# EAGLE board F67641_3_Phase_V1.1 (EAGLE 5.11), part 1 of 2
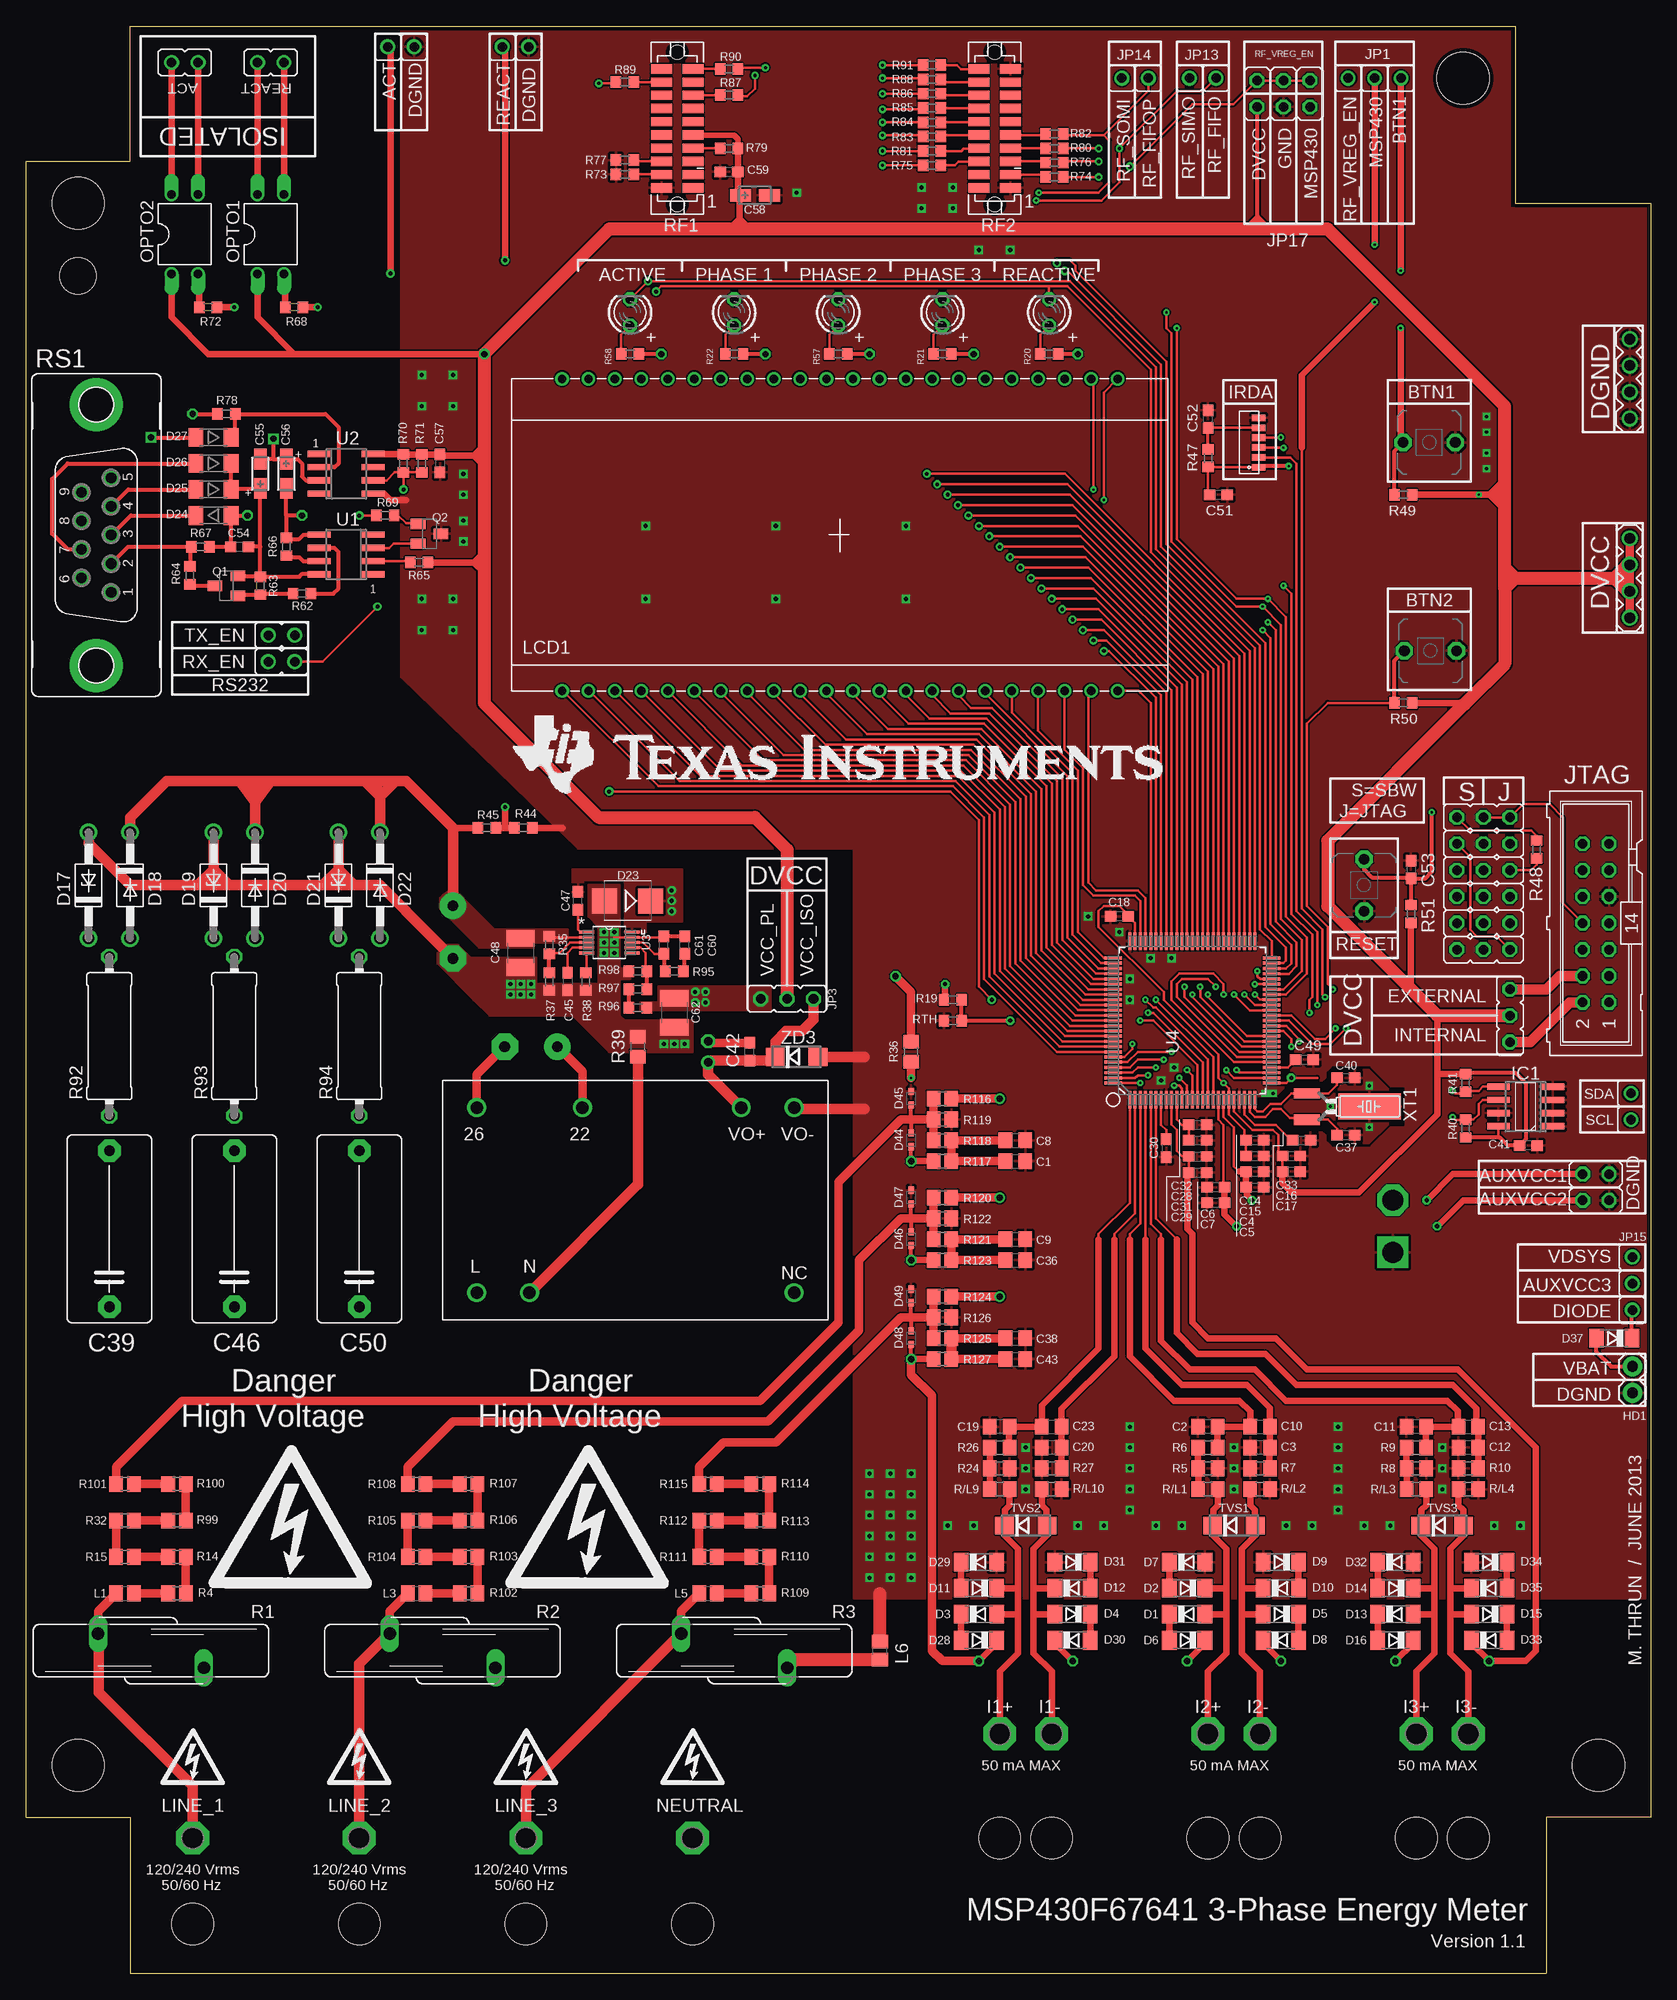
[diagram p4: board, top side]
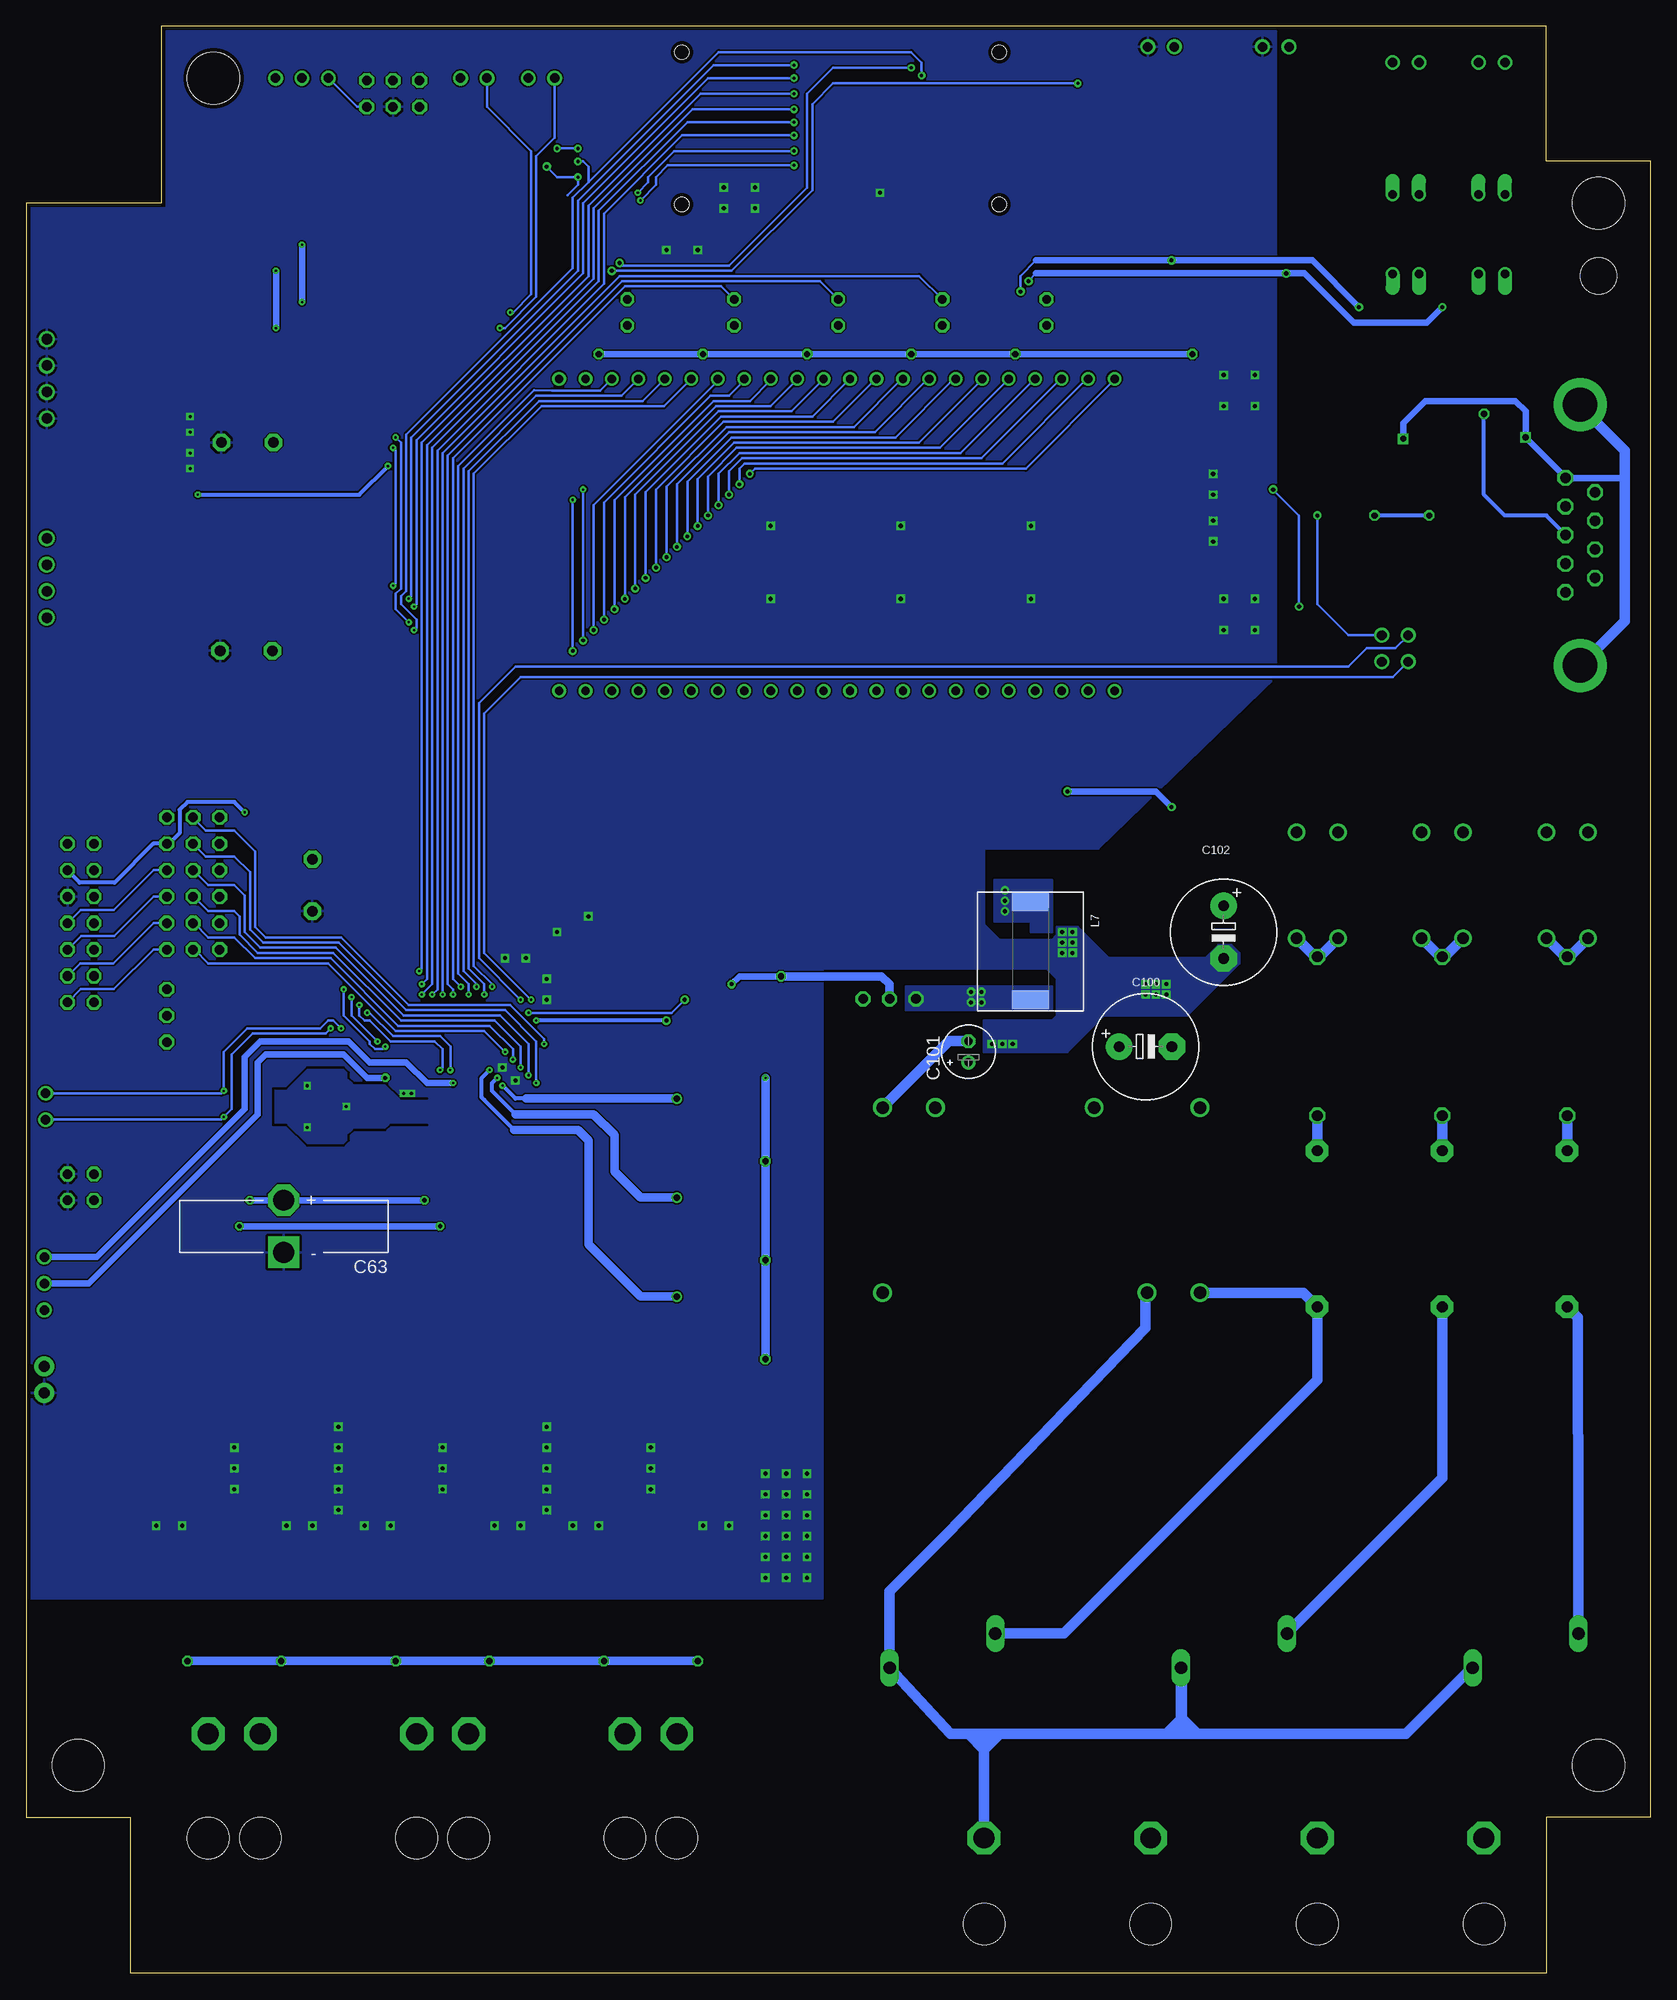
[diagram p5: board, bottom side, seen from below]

Size 156 x 187 mm. Coordinates in mm from the lower left corner, seen from the top.
Copper layers (1*16): Top 0.0356mm / dielectric 1.5011mm / Bottom 0.0356mm
Design rules "typical_4pcb": minimum track width 10mil, minimum drill 15mil, track to track 6mil, track to pad 6mil, pad to pad 6mil, via to via 6mil, smd to smd 6mil, copper to edge 15mil, drill to drill 8mil, minimum pad ring 10mil, minimum via ring 8mil, stop-mask expansion 4mil, vias tented up to drill 25mil, thermal gap 10mil
Holes 4 mm at 16,4.75 32,4.75 64,4.75 48,4.75 93.5,13 98.5,13 113.5,13 118.5,13 133.5,13 138.5,13
tRestrict: 20 lines
bRestrict: 19 lines

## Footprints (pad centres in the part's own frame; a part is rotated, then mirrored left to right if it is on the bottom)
JP1 = drill 0.914 round: 1 0,-1.27; 2 0,1.27
PBTH = drill 1.016 pad 1.676 octagon: 1 -0.001,0.001; 2 5.001,0.001
C0805 = smd 1.3 x 1.5: 1 -0.95,0; 2 0.95,0
C0603 = smd 1.1 x 1: 1 -0.85,0; 2 0.85,0
C15B8 = drill 1.016 pad 2.159 octagon: 1 -7.493,0; 2 7.493,0
C1210 = smd 1.6 x 2.7: 1 -1.4,0; 2 1.4,0
CT3216 = smd 2 x 1.2: + 1.4,0; - -1.4,0
CT3216' = smd 2 x 1.2: + -1.4,0; - 1.4,0
SUPERCAP = drill 2 square: GND 0,2.5 | drill 2 octagon: VCC 0,-2.5
E5-10,5 = drill 1.016 pad 2.54 round: + -2.54,0 | drill 1.016 pad 2.54 octagon: - 2.54,0
E2-5 = drill 0.813 pad 1.27 round: + -1.016,0 | drill 0.813 pad 1.27 octagon: - 1.016,0
3_PHASE_CASE = hole 5: 0,0; 146,0; 0,150; 133,162 | hole 3.5: 0,143
SOD80C = smd 1.4 x 1.8: A 1.7,0; C -1.7,0
DO41Z10 = drill 1.118 round: A 5.08,0; C -5.08,0
DO41-10 = drill 1.118 round: A 5.08,0; C -5.08,0
SMB = smd 2.4 x 2.4: A 2.2,0; C -2.2,0
SOD80 = smd 1.4 x 1.8: 1 -1.7,0; 2 1.7,0
SOD523 = smd 0.7 x 0.5: A 0.7,0; C -0.6,0
MA04-1 = drill 1.016 round: 1 -3.81,0; 2 -1.27,0; 3 1.27,0; 4 3.81,0
1X02 = drill 1.016 pad 1.88 round: 1 0,0; 2 2.54,0
P1-20 = drill 2.007 pad 3.15 octagon: TP 0,0
SO-08 = smd 0.6 x 2.2: 1 -1.905,-2.6; 2 -0.635,-2.6; 3 0.635,-2.6; 4 1.905,-2.6; 5 1.905,2.6; 6 0.635,2.6; 7 -0.635,2.6; 8 -1.905,2.6
TFBS4711 = smd 0.64 x 1.27: P$1 0.625,0.635; P$2 1.575,0.635; P$3 2.525,0.635; P$4 3.475,0.635; P$5 4.425,0.635; P$6 5.375,0.635
JP2 = drill 0.914 round: 1 -2.54,0; 2 0,0; 3 2.54,0
JP2' = drill 0.914 octagon: 1 -2.54,0; 2 0,0; 3 2.54,0
JP2Q = drill 0.914 octagon: 1 -1.27,-1.27; 2 -1.27,1.27; 3 1.27,-1.27; 4 1.27,1.27
JP3Q = drill 0.914 octagon: 1 -2.54,-1.27; 2 -2.54,1.27; 3 0,-1.27; 4 0,1.27; 5 2.54,-1.27; 6 2.54,1.27
ML14 = drill 0.914 octagon: 1 -7.62,-1.27; 2 -7.62,1.27; 3 -5.08,-1.27; 4 -5.08,1.27; 5 -2.54,-1.27; 6 -2.54,1.27; 7 0,-1.27; 8 0,1.27; 9 2.54,-1.27; 10 2.54,1.27; 11 5.08,-1.27; 12 5.08,1.27; 13 7.62,-1.27; 14 7.62,1.27
R0805 = smd 1.3 x 1.5: 1 -0.85,0; 2 0.85,0
INDUCTOR_POWER_SUPPLY_6779 = smd 3.556 x 1.778: 1 -3.81,-4.64; 2 -3.81,4.758
TI_160SEG_LCD = drill 0.8 round: 1 4.826,0; 2 7.366,0; 3 9.906,0; 4 12.446,0; 5 14.986,0; 6 17.526,0; 7 20.066,0; 8 22.606,0; 9 25.146,0; 10 27.686,0; 11 30.226,0; 12 32.766,0; 13 35.306,0; 14 37.846,0; 15 40.386,0; 16 42.926,0; 17 45.466,0; 18 48.006,0; 19 50.546,0; 20 53.086,0; 21 55.626,0; 22 58.166,0; 23 58.166,29.972; 24 55.626,29.972; 29 42.926,29.972; 30 40.386,29.972; 31 37.846,29.972; 32 35.306,29.972; 33 32.766,29.972; 34 30.226,29.972; 35 27.686,29.972; 36 25.146,29.972; 37 22.606,29.972; 38 20.066,29.972; 39 17.526,29.972; 40 14.986,29.972; 41 12.446,29.972; 42 9.906,29.972; 43 7.366,29.972; 44 4.826,29.972; COM0 45.466,29.972; COM1 48.006,29.972; COM2 50.546,29.972; COM3 53.086,29.972
LED3MM = drill 0.813 octagon: A -1.27,0; K 1.27,0
DIL04 = drill 0.813 offset: 1 -1.27,-3.81; 2 1.27,-3.81; 3 1.27,3.81; 4 -1.27,3.81
SOT23-BEC = smd 1 x 1.4: B -0.95,-1.1; C 0,1.1; E 0.95,-1.1
S20K275 = drill 1.194 long: 1 -1.651,-5.08; 2 1.651,5.08
R0805' = smd 1.3 x 1.5: 1 -0.95,0; 2 0.95,0
R0603 = smd 1 x 1.1: 1 -0.85,0; 2 0.85,0
0414/15 = drill 1.016 octagon: 1 -7.62,0; 2 7.62,0
TFM-110-02-SM-D-A-K = smd 2.032 x 0.889: 1 -1.524,5.715; 2 1.524,5.715; 3 -1.524,4.445; 4 1.524,4.445; 5 -1.524,3.175; 6 1.524,3.175; 7 -1.524,1.905; 8 1.524,1.905; 9 -1.524,0.635; 10 1.524,0.635; 11 -1.524,-0.635; 12 1.524,-0.635; 13 -1.524,-1.905; 14 1.524,-1.905; 15 -1.524,-3.175; 16 1.524,-3.175; 17 -1.524,-4.445; 18 1.524,-4.445; 19 -1.524,-5.715; 20 1.524,-5.715 | hole 1.359: 0,7.303; 0,-7.303
F09VP = drill 1.016 octagon: 1 5.486,1.422; 2 2.743,1.422; 3 0,1.422; 4 -2.743,1.422; 5 -5.486,1.422; 6 4.115,-1.422; 7 1.372,-1.422; 8 -1.372,-1.422; 9 -4.115,-1.422 | drill 3.302 pad 5.08 round: G1 -12.522,0; G2 12.522,0
DO214AC = smd 1.8 x 1.7: A 2.05,0; C -2.05,0
SO08 = smd 0.6 x 2.2: 1 -1.905,-2.6; 2 -0.635,-2.6; 3 0.635,-2.6; 4 1.905,-2.6; 5 1.905,2.6; 6 0.635,2.6; 7 -0.635,2.6; 8 -1.905,2.6
DGQ10_1P88X1P57 = smd 1.422 x 0.279: 1 -2.184,1; 2 -2.184,0.5; 3 -2.184,0; 4 -2.184,-0.5; 5 -2.184,-1; 6 2.184,-1; 7 2.184,-0.5; 8 2.184,0; 9 2.184,0.5; 10 2.184,1
PZ100 = smd 1.676 x 0.279: 1 -7.62,5.994; 2 -7.62,5.512; 3 -7.62,5.004; 4 -7.62,4.496; 5 -7.62,3.988; 6 -7.62,3.505; 7 -7.62,2.997; 8 -7.62,2.489; 9 -7.62,2.007; 10 -7.62,1.499; 11 -7.62,0.991; 12 -7.62,0.508; 13 -7.62,0; 14 -7.62,-0.508; 15 -7.62,-0.991; 16 -7.62,-1.499; 17 -7.62,-2.007; 18 -7.62,-2.489; 19 -7.62,-2.997; 20 -7.62,-3.505; 21 -7.62,-3.988; 22 -7.62,-4.496; 23 -7.62,-5.004; 24 -7.62,-5.512; 25 -7.62,-5.994; 51 7.62,-5.994; 52 7.62,-5.512; 53 7.62,-5.004; 54 7.62,-4.496; 55 7.62,-3.988; 56 7.62,-3.505; 57 7.62,-2.997; 58 7.62,-2.489; 59 7.62,-2.007; 60 7.62,-1.499; 61 7.62,-0.991; 62 7.62,-0.508; 63 7.62,0; 64 7.62,0.508; 65 7.62,0.991; 66 7.62,1.499; 67 7.62,2.007; 68 7.62,2.489; 69 7.62,2.997; 70 7.62,3.505; 71 7.62,3.988; 72 7.62,4.496; 73 7.62,5.004; 74 7.62,5.512; 75 7.62,5.994 | smd 0.279 x 1.676: 26 -5.994,-7.62; 27 -5.512,-7.62; 28 -5.004,-7.62; 29 -4.496,-7.62; 30 -3.988,-7.62; 31 -3.505,-7.62; 32 -2.997,-7.62; 33 -2.489,-7.62; 34 -2.007,-7.62; 35 -1.499,-7.62; 36 -0.991,-7.62; 37 -0.508,-7.62; 38 0,-7.62; 39 0.508,-7.62; 40 0.991,-7.62; 41 1.499,-7.62; 42 2.007,-7.62; 43 2.489,-7.62; 44 2.997,-7.62; 45 3.505,-7.62; 46 3.988,-7.62; 47 4.496,-7.62; 48 5.004,-7.62; 49 5.512,-7.62; 50 5.994,-7.62; 76 5.994,7.62; 77 5.512,7.62; 78 5.004,7.62; 79 4.496,7.62; 80 3.988,7.62; 81 3.505,7.62; 82 2.997,7.62; 83 2.489,7.62; 84 2.007,7.62; 85 1.499,7.62; 86 0.991,7.62; 87 0.508,7.62; 88 0,7.62; 89 -0.508,7.62; 90 -0.991,7.62; 91 -1.499,7.62; 92 -2.007,7.62; 93 -2.489,7.62; 94 -2.997,7.62; 95 -3.505,7.62; 96 -3.988,7.62; 97 -4.496,7.62; 98 -5.004,7.62; 99 -5.512,7.62; 100 -5.994,7.62
CUI_XR = drill 1.2 round: 22 10.16,0; 26 0,0; L 0,-17.78; N 5.08,-17.78; NC 30.48,-17.78; VO+ 25.4,0; VO- 30.48,0
CM200T = smd 1 x 2.5: P1 -1.25,-5; P2 1.25,-5 | smd 2.5 x 6: P3 0,1

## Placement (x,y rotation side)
ACT  [JP1]  15.25,183.5 90 top
BTN1  [PBTH]  137.25,147.01 180 top
BTN2  [PBTH]  137.36,127.01 180 top
C1  100nF  [C0805]  95,78 0 top
C2  47p  [C0805]  113.5,52.5 180 top
C3  47p  [C0805]  118.5,50.5 180 top
C4  4.7uF  [C0603]  118,77 0 top
C5  100nF  [C0603]  118,75.5 0 top
C6  4.7uF  [C0603]  114.25,75.5 180 top
C7  100nF  [C0603]  114.25,74 180 top
C8  10uF  [C0805]  95,80 0 top
C9  100nF  [C0805]  95,70.5 0 top
C10  15n  [C0805]  118.5,52.5 0 top
C11  47p  [C0805]  133.5,52.5 180 top
C12  47p  [C0805]  138.5,50.5 180 top
C13  15n  [C0805]  138.5,52.5 0 top
C14  4.7uF  [C0603]  118,80 0 top
C15  100nF  [C0603]  118,78.5 0 top
C16  4.7uF  [C0603]  121.5,78.5 0 top
C17  100nF  [C0603]  121.5,77 0 top
C18  0.1uF  [C0603]  105,101.5 180 top
C19  47p  [C0805]  93.5,52.5 180 top
C20  47p  [C0805]  98.5,50.5 180 top
C23  15n  [C0805]  98.5,52.5 0 top
C28  100nF  [C0603]  112.5,80 0 top
C29  4.7uF  [C0603]  112.5,76.9 0 top
C30  100nF  [C0603]  109.5,79.25 270 top
C31  100nF  [C0603]  112.5,78.45 0 top
C32  4.7uF  [C0603]  112.5,81.5 0 top
C33  470nF  [C0603]  122.5,80 0 top
C36  10uF  [C0805]  95,68.5 0 top
C37  12pF  [C0603]  126.75,80.5 0 top
C38  100nF  [C0805]  95,61 0 top
C39  0.22uF/305VAC  [C15B8]  8,71.5 90 top
C40  12pF  [C0603]  126.75,86 0 top
C41  0.1uF  [C0603]  144.25,79.5 180 top
C42  0.1uF  [C0603]  69.5,88.5 90 top
C43  10uF  [C0805]  95,59 0 top
C45  0.01uF  [C0603]  52,95.25 270 top
C46  0.22uF/305VAC  [C15B8]  20,71.5 90 top
C47  0.1uF  [C0603]  53,103 90 top
C48  2.2uF  [C1210]  47.5,98 270 top
C49  4.7uF  [C0603]  122.75,87.75 0 top
C50  0.22uF/305VAC  [C15B8]  32,71.5 90 top
C51  4.7uF  [C0603]  114.5,142 0 top
C52  0.1uF  [C0603]  113.5,149.25 90 top
C53  0.1uF  [C0603]  133,106 270 top
C54  0.1uF  [C0603]  20.5,137 0 top
C55  10uF  [CT3216]  22.5,144 270 top
C56  10uF  [CT3216]  25,144 90 top
C57  0.1uF  [C0603]  39.75,145 270 top
C58  10uF  [CT3216']  70,170.75 0 top
C59  0.1uF  [C0603]  67.5,173 0 top
C60  .056uF  [C0603]  63.25,98.75 90 top
C61  100pF  [C0603]  61.25,98.75 90 top
C62  47uF  [C1210]  62.25,92.25 270 top
C63  1F  [SUPERCAP]  131.25,71.75 180 bottom
C100  4.7u/400V  [E5-10,5]  48.5,89 0 bottom
C101  150uF  [E2-5]  65.5,88.5 90 bottom
C102  100uF/100V  [E5-10,5]  41,100 270 bottom
CASE1  3_PHASE_CASE  [3_PHASE_CASE]  5,20 0 top
D1  PMLL4148  [SOD80C]  111.5,34.5 0 top
D2  PMLL4148  [SOD80C]  111.5,37 180 top
D3  PMLL4148  [SOD80C]  91.5,34.5 0 top
D4  PMLL4148  [SOD80C]  100.5,34.5 180 top
D5  PMLL4148  [SOD80C]  120.5,34.5 180 top
D6  PMLL4148  [SOD80C]  111.5,32 180 top
D7  PMLL4148  [SOD80C]  111.5,39.5 0 top
D8  PMLL4148  [SOD80C]  120.5,32 0 top
D9  PMLL4148  [SOD80C]  120.5,39.5 180 top
D10  PMLL4148  [SOD80C]  120.5,37 0 top
D11  PMLL4148  [SOD80C]  91.5,37 180 top
D12  PMLL4148  [SOD80C]  100.5,37 0 top
D13  PMLL4148  [SOD80C]  131.5,34.5 0 top
D14  PMLL4148  [SOD80C]  131.5,37 180 top
D15  PMLL4148  [SOD80C]  140.5,34.5 180 top
D16  PMLL4148  [SOD80C]  131.5,32 180 top
D17  1N4757A  [DO41Z10]  6,104.5 90 top
D18  1N4007  [DO41-10]  10,104.5 270 top
D19  1N4757A  [DO41Z10]  18,104.5 90 top
D20  1N4007  [DO41-10]  22,104.5 270 top
D21  1N4757A  [DO41Z10]  30,104.5 90 top
D22  1N4007  [DO41-10]  34,104.5 270 top
D23  B160  [SMB]  57.75,103 180 top
D24  LL103A  [SOD80]  18,140 0 top
D25  LL103A  [SOD80]  18,142.5 180 top
D26  LL103A  [SOD80]  18,145 180 top
D27  LL103A  [SOD80]  18,147.5 180 top
D28  PMLL4148  [SOD80C]  91.5,32 180 top
D29  PMLL4148  [SOD80C]  91.5,39.5 0 top
D30  PMLL4148  [SOD80C]  100.5,32 0 top
D31  PMLL4148  [SOD80C]  100.5,39.5 180 top
D32  PMLL4148  [SOD80C]  131.5,39.5 0 top
D33  PMLL4148  [SOD80C]  140.5,32 0 top
D34  PMLL4148  [SOD80C]  140.5,39.5 180 top
D35  PMLL4148  [SOD80C]  140.5,37 0 top
D37  [SOD80C]  152.5,61 180 top
D44  1N4148DO35-7  [SOD523]  85,80 90 top
D45  1N4148DO35-7  [SOD523]  85,84 90 top
D46  1N4148DO35-7  [SOD523]  85,70.5 90 top
D47  1N4148DO35-7  [SOD523]  85,74.5 90 top
D48  1N4148DO35-7  [SOD523]  85,61 90 top
D49  1N4148DO35-7  [SOD523]  85,65 90 top
DGND  [MA04-1]  154,153.12 270 top
DVCC  [MA04-1]  154,134 270 top
HD1  [1X02]  154.25,55.75 90 top
I1+  TPPAD1-20  [P1-20]  93.5,23 0 top
I1-  TPPAD1-20  [P1-20]  98.5,23 0 top
I2+  TPPAD1-20  [P1-20]  113.5,23 0 top
I2-  TPPAD1-20  [P1-20]  118.5,23 0 top
I3+  TPPAD1-20  [P1-20]  133.5,23 0 top
I3-  TPPAD1-20  [P1-20]  138.5,23 0 top
IC1  24C02CSN  [SO-08]  144,83.25 90 top
IRDA  TFBS4711-TT1  [TFBS4711]  119,144 90 top
JP1  [JP2]  129.5,182 180 top
JP2  [JP1]  154.12,83.25 0 top
JP3  [JP2']  73.08,93.58 180 top
JP4  [JP2']  139.95,111.02 0 top
JP5  [JP2']  139.95,108.48 0 top
JP6  [JP2']  139.95,105.94 0 top
JP7  [JP2']  139.95,103.4 0 top
JP8  [JP2']  139.95,100.86 0 top
JP9  [JP2']  139.95,98.32 0 top
JP10  [JP2']  142.49,91.97 90 top
JP11  [JP1]  47,185 270 top
JP12  [JP1]  36,185 270 top
JP13  [JP1]  113,182 270 top
JP14  [JP1]  106.5,182 270 top
JP15  [JP2]  154.25,66.25 90 top
JP16  [JP2Q]  150.75,75.5 270 top
JP17  [JP3Q]  120.75,180.5 180 top
JTAG  [ML14]  150.75,100.86 90 top
L1  EXCML20A  [R0805]  9.5,36.5 0 top
L3  EXCML20A  [R0805]  37.5,36.5 0 top
L5  EXCML20A  [R0805]  65.5,36.5 0 top
L6  EXCML20A  [R0805]  82,31 90 top
L7  1mH  [INDUCTOR_POWER_SUPPLY_6779]  63.37,98.28 180 bottom
LCD1  TI_160SEG_LCD  [TI_160SEG_LCD]  46.65,123.16 0 top
LED_ACT  [LED3MM]  58,159.5 90 top
LED_PHASE_1  [LED3MM]  68,159.5 90 top
LED_PHASE_2  [LED3MM]  78,159.5 90 top
LED_PHASE_3  [LED3MM]  88,159.5 90 top
LED_REACT  [LED3MM]  98.25,159.5 90 top
LINE_1  TPPAD1-20  [P1-20]  16,13 90 top
LINE_2  TPPAD1-20  [P1-20]  32,13 90 top
LINE_3  TPPAD1-20  [P1-20]  48,13 90 top
NEUTRAL  TPPAD1-20  [P1-20]  64,13 90 top
OPTO1  TIL191  [DIL04]  23.5,167 0 top
OPTO2  TIL191  [DIL04]  15.25,167 0 top
Q1  BC857BSMD  [SOT23-BEC]  19.25,133.25 90 top
Q2  BC857BSMD  [SOT23-BEC]  38.75,138.25 270 top
R1  S20K275  [S20K275]  12,31 90 top
R2  S20K275  [S20K275]  40,31 90 top
R3  S20K275  [S20K275]  68,31 90 top
R4  1M  [R0805]  14.5,36.5 180 top
R5  12.4  [R0805']  113.5,48.5 180 top
R6  1K  [R0805']  113.5,50.5 0 top
R7  1K  [R0805']  118.5,48.5 0 top
R8  12.4  [R0805']  133.5,48.5 180 top
R9  1K  [R0805']  133.5,50.5 0 top
R10  1K  [R0805']  138.5,48.5 0 top
R14  1M  [R0805]  14.5,40 0 top
R15  1M  [R0805]  9.5,40 0 top
R19  10K  [R0603]  89,93.5 180 top
R20  100  [R0603]  98.25,155.5 180 top
R21  100  [R0603]  88,155.5 180 top
R22  100  [R0603]  68,155.5 180 top
R24  12.4  [R0805']  93.5,48.5 180 top
R26  1K  [R0805']  93.5,50.5 0 top
R27  1K  [R0805']  98.5,48.5 0 top
R32  1M  [R0805]  9.5,43.5 180 top
R35  1M  [R0603]  50.25,98.75 90 top
R36  10R  [R0805']  84.99,88.51 270 top
R37  33.2K  [R0603]  50.25,95.25 90 top
R38  1M  [R0603]  53.75,95.25 90 top
R39  0  [R0805']  58.75,89 90 top
R40  10K  [R0603]  138.25,81.12 270 top
R41  10K  [R0603]  138.25,85.5 90 top
R44  DNP  [R0603]  47.75,110 180 top
R45  DNP  [R0603]  44.25,110 180 top
R47  47  [R0603]  113.5,145.5 90 top
R48  330  [R0603]  145.06,107.94 90 top
R49  100K  [R0603]  132.25,142 180 top
R50  100K  [R0603]  132.25,122 180 top
R51  47K  [R0603]  133,101.75 90 top
R57  100  [R0603]  78,155.5 180 top
R58  100  [R0603]  58,155.5 180 top
R62  1K  [R0603]  26.5,132.5 180 top
R63  10K  [R0603]  22.5,133.25 90 top
R64  220  [R0603]  15.75,134.25 270 top
R65  68  [R0603]  37.75,135.5 180 top
R66  DNP  [R0603]  25,137 90 top
R67  1.5K  [R0603]  16.75,137 180 top
R68  1K  [R0603]  25.75,160 180 top
R69  2.2K  [R0603]  34.5,140 0 top
R70  DNP  [R0603]  36.25,145 90 top
R71  2.2K  [R0603]  38,145 270 top
R72  1K  [R0603]  17.5,160 180 top
R73  0  [R0603]  57.5,172.75 180 top
R74  0  [R0603]  98.75,172.5 180 top
R75  0  [R0603]  87,173.62 180 top
R76  0  [R0603]  98.75,173.88 180 top
R77  0  [R0603]  57.5,174.12 180 top
R78  1K  [R0603]  19.25,149.75 180 top
R79  0  [R0603]  67.5,175.25 180 top
R80  0  [R0603]  98.75,175.25 180 top
R81  0  [R0603]  87,175 180 top
R82  0  [R0603]  98.75,176.62 180 top
R83  0  [R0603]  87,176.38 180 top
R84  0  [R0603]  87,177.75 180 top
R85  0  [R0603]  87,179.12 180 top
R86  0  [R0603]  87,180.5 180 top
R87  0  [R0603]  67.5,180.38 180 top
R88  0  [R0603]  87,181.88 180 top
R89  0  [R0603]  57.5,181.62 180 top
R90  0  [R0603]  67.5,182.88 180 top
R91  0  [R0603]  87,183.25 180 top
R92  100  [0414/15]  8,90 90 top
R93  100  [0414/15]  20,90 90 top
R94  100  [0414/15]  32,90 90 top
R95  22.1K  [R0603]  62.25,96.25 180 top
R96  51.1  [R0603]  58.75,92.75 0 top
R97  31.6K  [R0603]  58.75,94.5 180 top
R98  10K  [R0603]  58.75,96.25 0 top
R99  1M  [R0805]  14.5,43.5 180 top
R100  1M  [R0805]  14.5,47 0 top
R101  1M  [R0805]  9.5,47 0 top
R102  1M  [R0805]  42.5,36.5 180 top
R103  1M  [R0805]  42.5,40 0 top
R104  1M  [R0805]  37.5,40 0 top
R105  1M  [R0805]  37.5,43.5 180 top
R106  1M  [R0805]  42.5,43.5 180 top
R107  1M  [R0805]  42.5,47 0 top
R108  1M  [R0805]  37.5,47 0 top
R109  1M  [R0805]  70.5,36.5 180 top
R110  1M  [R0805]  70.5,40 0 top
R111  1M  [R0805]  65.5,40 0 top
R112  1M  [R0805]  65.5,43.5 180 top
R113  1M  [R0805]  70.5,43.5 180 top
R114  1M  [R0805]  70.5,47 0 top
R115  1M  [R0805]  65.5,47 0 top
R116  1K  [R0805]  88,84 0 top
R117  10  [R0805]  88,78 0 top
R118  20K  [R0805]  88,80 180 top
R119  10K  [R0805]  88,82 180 top
R120  1K  [R0805]  88,74.5 0 top
R121  20K  [R0805]  88,70.5 180 top
R122  10K  [R0805]  88,72.5 180 top
R123  10  [R0805]  88,68.5 0 top
R124  1K  [R0805]  88,65 0 top
R125  20K  [R0805]  88,61 180 top
R126  10K  [R0805]  88,63 180 top
R127  10  [R0805]  88,59 0 top
R/L1  0  [R0805']  113.5,46.5 0 top
R/L2  0  [R0805']  118.5,46.5 180 top
R/L3  0  [R0805']  133.5,46.5 0 top
R/L4  0  [R0805']  138.5,46.5 180 top
R/L9  0  [R0805']  93.5,46.5 0 top
R/L10  0  [R0805']  98.5,46.5 180 top
REACT  [JP1]  23.5,183.5 90 top
RESET  [PBTH]  128.5,107 270 top
RF1  [TFM-110-02-SM-D-A-K]  62.54,177.17 180 top
RF2  [TFM-110-02-SM-D-A-K]  93.02,177.17 180 top
RS1  [F09VP]  6.75,138.12 270 top
RTH  10K Thermistor  [R0603]  89,91.5 0 top
RX_EN  [JP1]  24.54,125.97 90 top
TVS1  SMAJ5.0CA  [DO214AC]  116,43 0 top
TVS2  SMAJ5.0CA  [DO214AC]  96,43 0 top
TVS3  SMAJ5.0CA  [DO214AC]  136,43 0 top
TX_EN  [JP1]  24.54,128.51 90 top
U1  PS8802  [SO08]  30.75,136.25 90 top
U2  PS8802  [SO08]  30.75,144 270 top
U3  TPS54060_DGQ_10  [DGQ10_1P88X1P57]  56,99 0 top
U4  MSP430F67641_PZ_100  [PZ100]  112,91.5 90 top
U$1  CUI_XR  [CUI_XR]  43.27,83.15 0 top
XT1  [CM200T]  128,83.25 270 top
ZD3  SMAJ5.0ABCT  [DO214AC]  74,88 0 top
